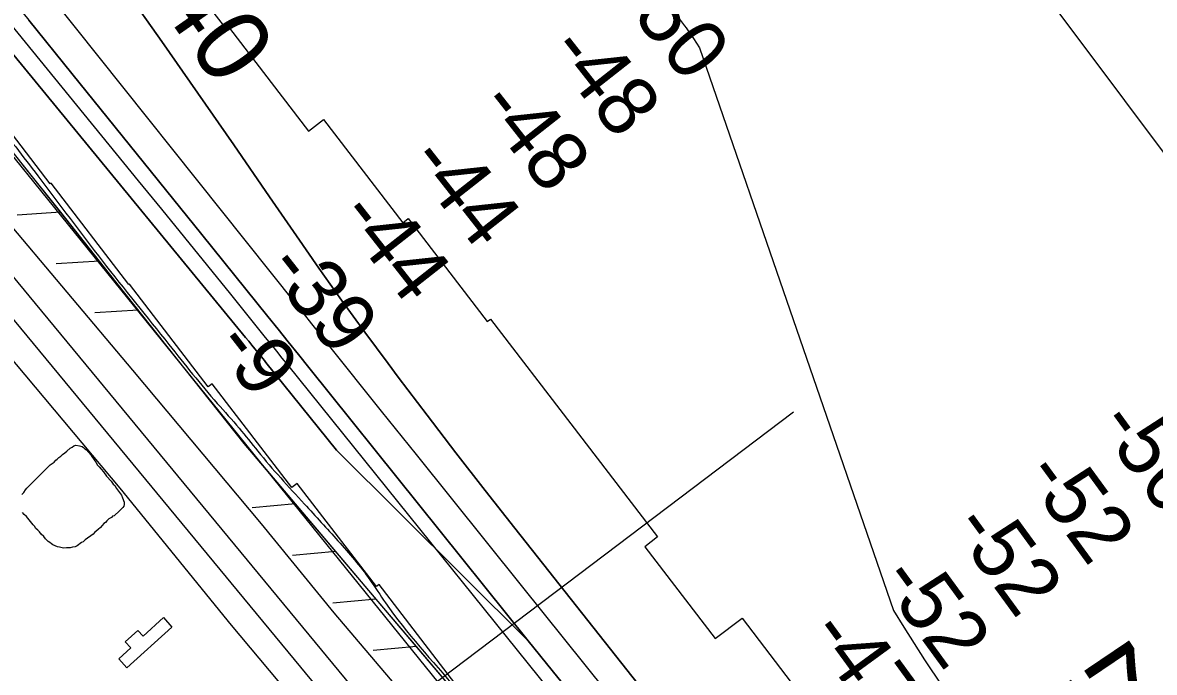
# Model space of a CAD drawing. Extents: x 3887375 to 3925618, y 296674 to 322633.
# Drawn here: x 3900685 to 3901955, y 303069 to 303798 of the extents above; entities that cross this region are included whole.
import ezdxf

# ---------------------------------------------------------------- set-up
doc = ezdxf.new("R2010")
doc.units = 0
for name, color, linetype in [('V-BLDG-OTLN', 7, 'Continuous'), ('V-LEVE-TOET', 7, 'Continuous'), ('V-RIVR-EDGE', 7, 'Continuous'), ('V-RIVR-RANG', 7, 'Continuous'), ('V-RRAP-FSHR', 7, 'Continuous'), ('V-RRAP-RVMT', 7, 'Continuous'), ('V-SITE-VEGE', 7, 'Continuous'), ('V-SURV-IDEN', 7, 'Continuous'), ('V-SURV-LINE', 7, 'Continuous'), ('V-TOPO-DPTH', 7, 'Continuous'), ('V-TOPO-MAJR', 7, 'Continuous'), ('V-TOPO-MAJR-IDEN', 7, 'Continuous'), ('V-TOPO-MINR', 7, 'Continuous')]:
    doc.layers.add(name, color=color, linetype=linetype)

msp = doc.modelspace()

# ---------------------------------------------------------------- linework, layer by layer
at = {"layer": 'V-BLDG-OTLN'}
msp.add_lwpolyline([(3900852.6, 303120.2), (3900802, 303074.5), (3900792.9, 303084.5), (3900806.5, 303096.8), (3900800.2, 303103.8), (3900814.2, 303116.5), (3900820.1, 303110.1), (3900843, 303130.8)], close=True, dxfattribs=at)
at = {"layer": 'V-LEVE-TOET'}
for points in [[(3901707.7, 302278.6), (3901647.7, 302352.6), (3901568.6, 302454.8), (3901489.4, 302571.2), (3901419.6, 302666.9), (3901350.9, 302753.6), (3901260.8, 302865.9), (3901184, 302961.1), (3901104.1, 303054.3), (3901034.7, 303136), (3900953.2, 303236.1), (3900808.8, 303408.5), (3900661.4, 303583.6), (3900535.6, 303736.4), (3900409.9, 303890.7), (3900289.1, 304039.5), (3900169.5, 304191.5), (3900063.8, 304326.3), (3899979, 304436.6), (3899860.4, 304585.9), (3899743.5, 304733.3)], [(3901593.3, 302276.6), (3901551.2, 302327.1), (3901473.8, 302430.8), (3901390.8, 302544.9), (3901295.5, 302675.3), (3901201.5, 302790.1), (3901115.9, 302885.4), (3901059.3, 302956.1), (3900993.1, 303034.3), (3900919.3, 303122.2), (3900794.4, 303275.9), (3900678.1, 303415), (3900578.2, 303534), (3900459.7, 303676.1), (3900342.1, 303815.9), (3900217.2, 303973.4), (3900106.8, 304107.3), (3900018.3, 304237.4), (3899953.6, 304320.1), (3899883.4, 304409.2), (3899779.4, 304538), (3899658.3, 304689.7)]]:
    msp.add_lwpolyline(points, dxfattribs=at)
at = {"layer": 'V-RIVR-EDGE'}
msp.add_spline([(3894498, 310522.4), (3894530, 310496.1), (3894553.8, 310474.7), (3894579.9, 310451.3), (3894614.8, 310419.2), (3894633.2, 310400.7), (3894662.8, 310372.4), (3894685.1, 310353.4), (3894692.4, 310347.1), (3894709.8, 310328.1), (3894746.6, 310285.3), (3894785.8, 310252.2), (3894809.6, 310225.9), (3894830.4, 310205.4), (3894852.7, 310189.9), (3894866.7, 310171.8), (3894915.2, 310120.3), (3894950.1, 310083.7), (3894971.4, 310062.8), (3894999, 310039.4), (3895025.2, 310017), (3895052.8, 309992.7), (3895093, 309952.3), (3895110.9, 309932.8), (3895141.4, 309903.1), (3895188.9, 309855.9), (3895222.8, 309821.3), (3895255.8, 309784.3), (3895319.2, 309722.5), (3895350.7, 309688.4), (3895358.4, 309676.3), (3895364.7, 309669.4), (3895374.9, 309663.1), (3895389, 309650.4), (3895410.8, 309628.1), (3895448.5, 309583.3), (3895480.5, 309554.1), (3895503.8, 309527.8), (3895533.8, 309499.5), (3895577.4, 309454.8), (3895606.9, 309425.5), (3895653.5, 309378.8), (3895685.9, 309349.1), (3895719.8, 309314.5), (3895749.4, 309285.8), (3895790.6, 309242.5), (3895837.1, 309195.8), (3895863.7, 309164.1), (3895900, 309127.6), (3895944.1, 309081.4), (3895955.7, 309070.7), (3895974.6, 309054.6), (3896002.3, 309033.1), (3896032.8, 309003.9), (3896062.8, 308972.3), (3896082.7, 308950.4), (3896119.5, 308911.9), (3896139.3, 308892.5), (3896152, 308889.5), (3896163.1, 308883.7), (3896167.9, 308873.9), (3896170.3, 308862.3), (3896184.4, 308844.3), (3896211, 308816), (3896224.1, 308810.2), (3896236.7, 308802.4), (3896249.8, 308786.8), (3896255.6, 308776.6), (3896270.6, 308766.4), (3896280.3, 308753.2), (3896295.8, 308737.2), (3896375.3, 308661.2), (3896425.2, 308610.1), (3896464.4, 308570.6), (3896519.6, 308515.6), (3896548.7, 308483), (3896563.2, 308467.5), (3896597.6, 308430.9), (3896635.9, 308396.4), (3896666.4, 308365.7), (3896681.4, 308349.6), (3896712.4, 308320.4), (3896746.3, 308287.3), (3896777.4, 308260), (3896801.6, 308235.7), (3896820.5, 308215.3), (3896842.8, 308195.3), (3896851.5, 308181.2), (3896882.5, 308148.6), (3896918.8, 308116.4), (3896962.9, 308074.6), (3896997.8, 308033.2), (3897029.2, 307998.6), (3897042.3, 307985), (3897083.5, 307945.6), (3897107.2, 307918.3), (3897123.2, 307898.8), (3897130, 307898.8), (3897142.1, 307893), (3897146, 307882.3), (3897149.9, 307874), (3897162.9, 307860.4), (3897188.6, 307833.1), (3897229.3, 307788.8), (3897267.6, 307752.3), (3897300.5, 307715.8), (3897334.4, 307680.3), (3897361.5, 307651.1), (3897384.8, 307628.2), (3897411.4, 307599), (3897445.8, 307563.4), (3897494.3, 307516.7), (3897543.2, 307462.7), (3897584.8, 307418.4), (3897609, 307394), (3897646.8, 307355.6), (3897678.8, 307323.9), (3897715.1, 307290.3), (3897752, 307253.3), (3897767, 307236.3), (3897837.7, 307158.4), (3897886.6, 307104.4), (3897936, 307048.4), (3897965.5, 307015.3), (3898010.6, 306970.1), (3898027.5, 306949.1), (3898045, 306936), (3898063.9, 306914.1), (3898089, 306882.5), (3898117.1, 306854.7), (3898160.2, 306801.2), (3898195.6, 306763.7), (3898235.8, 306719.9), (3898261.5, 306693.6), (3898297.3, 306650.8), (3898332.7, 306612.3), (3898369.9, 306568), (3898397.5, 306534.9), (3898422.2, 306505.8), (3898462.9, 306455.1), (3898495.3, 306417.2), (3898522, 306382.2), (3898601.4, 306284.3), (3898652.2, 306228.4), (3898693.4, 306177.3), (3898729.7, 306130.6), (3898777.1, 306074.1), (3898825.5, 306014.3), (3898848.8, 305986), (3898904, 305917.4), (3898957.2, 305854.7), (3898984.4, 305818.2), (3899049.7, 305744.7), (3899107.8, 305679.4), (3899129.1, 305651.7), (3899142.7, 305630.3), (3899156.2, 305611.8), (3899175.1, 305588), (3899224, 305529.6), (3899256, 305493.6), (3899288.9, 305449.3), (3899312.6, 305415.2), (3899375.6, 305336.9), (3899410.9, 305296), (3899442.8, 305252.2), (3899470.4, 305211.9), (3899531.4, 305133.5), (3899579.3, 305071.2), (3899616.1, 305026), (3899647.1, 304986.1), (3899690.7, 304931.1), (3899729.4, 304876.6), (3899753.6, 304846.9), (3899770.6, 304821.6), (3899817.5, 304755.5), (3899845.6, 304713.2), (3899868.3, 304677.2), (3899889.6, 304650.4), (3899911.4, 304623.6), (3899955.4, 304569.1), (3899987.4, 304526.8), (3900012.6, 304494.2), (3900025.6, 304476.2), (3900037.2, 304456.8), (3900061.9, 304431.9), (3900070.7, 304424.1), (3900074.5, 304414.4), (3900075, 304404.2), (3900073, 304397.9), (3900071.5, 304388.7), (3900071.5, 304383.8), (3900075.9, 304379), (3900087.1, 304374.1), (3900096.3, 304367.7), (3900108.4, 304362.4), (3900117.1, 304353.6), (3900140.8, 304326.3), (3900165.5, 304299.1), (3900226.1, 304227.6), (3900277.9, 304164.3), (3900320, 304105.9), (3900352.4, 304062.6), (3900384.4, 304023.2), (3900411.5, 303988.2), (3900438.1, 303954.1), (3900462.8, 303926.8), (3900556.2, 303812.5), (3900597.9, 303762.9), (3900633.7, 303716.6), (3900652.6, 303691.3), (3900702, 303626.6), (3900774.6, 303530.8), (3900849.1, 303437.3), (3900903.4, 303371.2), (3900928.1, 303343.4), (3900948.9, 303317.6), (3901001.2, 303258.3), (3901038.9, 303216.9), (3901074.8, 303173.1), (3901092.2, 303147.3), (3901171.6, 303050.5), (3901205, 303008.6), (3901238.4, 302968.2), (3901274.7, 302927.8), (3901303.3, 302893.8), (3901344, 302847.5), (3901366.7, 302816.4), (3901404.5, 302770.2), (3901454.4, 302715.2), (3901507.2, 302659.2), (3901551.7, 302608.1), (3901584.7, 302570.6), (3901650, 302491.3), (3901681, 302443.6), (3901717.8, 302388.2), (3901785.5, 302298.2), (3901789.5, 302293.3)], degree=3, dxfattribs=at)
at = {"layer": 'V-RIVR-RANG'}
msp.add_line((3901087.4, 303011.9), (3901550.1, 303361.6), dxfattribs=at)
at = {"layer": 'V-RRAP-FSHR'}
for p, q in [((3900727.8, 303585.6), (3900679, 303582.6)), ((3900771.3, 303530.7), (3900722.6, 303527.8)), ((3900814.8, 303475.9), (3900766.1, 303473)), ((3900991.2, 303258.5), (3900942.6, 303254)), ((3901036.5, 303205.1), (3900987.8, 303200.6)), ((3901081.7, 303151.7), (3901033.1, 303147.2)), ((3901127, 303098.3), (3901078.4, 303093.8))]:
    msp.add_line(p, q, dxfattribs=at)
for points in [[(3891468.4, 312810.1), (3891592.1, 312735.5), (3892299.9, 312230.2), (3893039.2, 311719.3), (3893631.6, 311277.1), (3894117.7, 310846), (3894636.9, 310371.6), (3895242, 309786.8), (3895348.8, 309658.3), (3895604.3, 309398.3), (3896430.2, 308555.1), (3897023.9, 307973.7), (3897641.6, 307335.1), (3898033.6, 306930.9), (3898562.2, 306317.9), (3899280.4, 305434.2), (3899629.7, 304981.5), (3900046.2, 304414.8), (3900422.7, 303959.4), (3901188.8, 303011.8), (3901775.8, 302279.8)], [(3901789.3, 302283.8), (3901580.6, 302550.1), (3901486.3, 302669.7), (3901336.9, 302850.8), (3900933.8, 303326.1), (3900183.2, 304271.3)], [(3900727.8, 303585.6), (3900684.2, 303640.4)], [(3900771.3, 303530.7), (3900727.8, 303585.6)], [(3900814.8, 303475.9), (3900771.3, 303530.7)], [(3900840.5, 303443.6), (3900814.8, 303475.9)], [(3900991.2, 303258.5), (3900945.9, 303311.9)], [(3901036.5, 303205.1), (3900991.2, 303258.5)], [(3901081.7, 303151.7), (3901036.5, 303205.1)], [(3901127, 303098.3), (3901081.7, 303151.7)], [(3901172.3, 303044.9), (3901127, 303098.3)]]:
    msp.add_lwpolyline(points, dxfattribs=at)
at = {"layer": 'V-RRAP-RVMT'}
for p, q in [((3900827.2, 303903.9), (3900914.2, 303790.3)), ((3900914.2, 303790.3), (3900917, 303792.4)), ((3900917, 303792.4), (3901005.7, 303676.7)), ((3900716, 303617.4), (3900627.6, 303732.8)), ((3901005.7, 303676.7), (3901022.8, 303689.7)), ((3901022.8, 303689.7), (3901111.5, 303573.9)), ((3900717, 303618.3), (3900716, 303617.4)), ((3900804.2, 303504.5), (3900717, 303618.3)), ((3901111.5, 303573.9), (3901117.7, 303578.7)), ((3901117.7, 303578.7), (3901206.4, 303463)), ((3900804.8, 303504.9), (3900804.2, 303504.5)), ((3900893.2, 303389.6), (3900804.8, 303504.9)), ((3901206.4, 303463), (3901209.9, 303465.7)), ((3901209.9, 303465.7), (3901300, 303348.1)), ((3900897.8, 303393.1), (3900893.2, 303389.6)), ((3900987, 303276.8), (3900897.8, 303393.1)), ((3901300, 303348.1), (3901397.3, 303221.3)), ((3900993.2, 303281.5), (3900987, 303276.8)), ((3901082.1, 303165.6), (3900993.2, 303281.5)), ((3901397.3, 303221.3), (3901383.2, 303210.4)), ((3901383.2, 303210.4), (3901462.3, 303107.2)), ((3901085, 303167.9), (3901082.1, 303165.6)), ((3901174.8, 303050.8), (3901085, 303167.9)), ((3901462.3, 303107.2), (3901492.4, 303130.1)), ((3901492.4, 303130.1), (3901589.5, 303003.4))]:
    msp.add_line(p, q, dxfattribs=at)
at = {"layer": 'V-SITE-VEGE'}
msp.add_lwpolyline([(3900684.2, 303268.9), (3900686.2, 303271.3), (3900688.2, 303274.2), (3900689.8, 303276.2), (3900694.5, 303281.1), (3900696.9, 303283.1), (3900709.6, 303296), (3900711.9, 303298.1), (3900715.9, 303302.1), (3900720.3, 303305.4), (3900722.3, 303307.4), (3900723.8, 303308.6), (3900725.8, 303310.6), (3900727.8, 303311.9), (3900729.8, 303313.9), (3900732.2, 303315.9), (3900734.6, 303317.5), (3900738.5, 303320.8), (3900740.5, 303322), (3900742.5, 303323.6), (3900744.9, 303324.5), (3900748.9, 303323.7), (3900751.7, 303322.9), (3900753.3, 303321.8), (3900755, 303320.2), (3900756.6, 303319), (3900761.4, 303313.4), (3900762.7, 303311.5), (3900764.7, 303309.1), (3900765.9, 303306.7), (3900767.1, 303305.1), (3900769.2, 303301.9), (3900770.8, 303299.9), (3900773.2, 303297.5), (3900775.7, 303294.4), (3900779.3, 303289.6), (3900784.2, 303284.1), (3900786.6, 303280.5), (3900788.3, 303278.9), (3900790.3, 303275.7), (3900796, 303268.2), (3900797.2, 303265.4), (3900798.9, 303260.2), (3900798.9, 303257.8), (3900798.5, 303255.8), (3900797.3, 303254.2), (3900793.8, 303250.5), (3900787.8, 303245.2), (3900785.8, 303244.8), (3900784.6, 303243.2), (3900781.9, 303241.6), (3900779.5, 303239.5), (3900777.9, 303237.5), (3900776.3, 303236.3), (3900774.3, 303234.3), (3900772.4, 303231.9), (3900769.6, 303229.8), (3900767.6, 303227.8), (3900766, 303226.6), (3900764, 303224.6), (3900755.3, 303218.1), (3900752.9, 303216), (3900750.9, 303215.2), (3900746.2, 303211.5), (3900743.8, 303210.3), (3900741, 303209.9), (3900738.2, 303209.1), (3900734.2, 303209), (3900731.4, 303208.6), (3900729.4, 303209), (3900726.5, 303209.7), (3900724.1, 303210.1), (3900721.7, 303211.3), (3900718.9, 303212.4), (3900717.3, 303213.6), (3900715.7, 303215.2), (3900713.7, 303216.4), (3900710.8, 303219.2), (3900708.8, 303221.9), (3900706, 303224.3), (3900703.9, 303227.1), (3900701.9, 303229.1), (3900699.9, 303230.7), (3900698.2, 303233.4), (3900697, 303235), (3900689.3, 303244.2), (3900686.9, 303246.5), (3900684.9, 303248.9)], dxfattribs=at)
at = {"layer": 'V-SURV-LINE'}
for points in [[(3900476.9, 303751.8), (3901318.4, 302733.5)], [(3901295.2, 302714.4), (3900453.8, 303732.6)]]:
    msp.add_lwpolyline(points, dxfattribs=at)
at = {"layer": 'V-TOPO-DPTH'}
for points in [[(3899996.1, 304666.3), (3900007, 304652.8), (3900017.9, 304639.3), (3900200.6, 304411.9), (3900246.8, 304354.3), (3900293, 304296.8), (3900339.1, 304239.2), (3900385.2, 304181.5), (3900439.6, 304113.3), (3900458.5, 304089.8), (3900477.3, 304066.3), (3900496.2, 304042.8), (3900515.2, 304019.4), (3900691.8, 303801.4), (3900740.4, 303741.2), (3900789, 303681.1), (3900837.6, 303620.9), (3900886.1, 303560.7), (3900960, 303468.8), (3900971.6, 303454.5), (3900983.1, 303440.2), (3900994.6, 303425.9), (3901006.1, 303411.6), (3901252.4, 303104.9)], [(3901252.4, 303104.9), (3901037.1, 303318.9), (3900958, 303417.1), (3900957.2, 303418.2), (3900956.3, 303419.3), (3900954.6, 303421.4), (3900949.3, 303428), (3900945.7, 303432.3), (3900942.2, 303436.6), (3900938.7, 303440.9), (3900935.1, 303445.3), (3900486.7, 303991.6), (3900409.6, 304087.8)], [(3900687.7, 303863.7), (3900990.3, 303484.2), (3900999.7, 303472.4), (3901009.1, 303460.6), (3901018.6, 303448.8), (3901028, 303437), (3901087.5, 303362.6), (3901126.6, 303313.7), (3901165.8, 303264.7), (3901205.1, 303215.8), (3901244.3, 303166.9), (3901411.8, 302958.6), (3901426.4, 302940.7), (3901441.2, 302922.9), (3901456.2, 302905.4), (3901471.4, 302887.9), (3901558, 302789.9), (3901587.8, 302757.3), (3901946.4, 302370.6), (3901982.7, 302326)], [(3900687.7, 303863.7), (3900990.3, 303484.2), (3900999.7, 303472.4), (3901009.1, 303460.6), (3901018.6, 303448.8), (3901028, 303437), (3901087.5, 303362.6), (3901126.6, 303313.7), (3901165.8, 303264.7), (3901205.1, 303215.8), (3901244.3, 303166.9), (3901411.8, 302958.6), (3901426.4, 302940.7), (3901441.2, 302922.9), (3901456.2, 302905.4), (3901471.4, 302887.9), (3901558, 302789.9), (3901587.8, 302757.3), (3901946.4, 302370.6), (3901982.7, 302326)], [(3901955.2, 302446.5), (3901501.7, 302905.5), (3901489.7, 302917.2), (3901476.5, 302931), (3901471.6, 302936.2), (3901466.8, 302941.5), (3901462.2, 302947), (3901457.7, 302952.5), (3901237.3, 303231.2), (3901204.2, 303273.3), (3901171.3, 303315.6), (3901138.8, 303358.1), (3901106.5, 303400.8), (3901095.2, 303415.8), (3901068.9, 303451.3), (3901042.9, 303487), (3901017.5, 303523), (3900992.3, 303559.2), (3900962.2, 303603.1), (3900922.1, 303661.3), (3900881.8, 303719.4), (3900841.1, 303777.3), (3900800.3, 303835.1)], [(3901955.2, 302446.5), (3901501.7, 302905.5), (3901489.7, 302917.2), (3901476.5, 302931), (3901471.6, 302936.2), (3901466.8, 302941.5), (3901462.2, 302947), (3901457.7, 302952.5), (3901237.3, 303231.2), (3901204.2, 303273.3), (3901171.3, 303315.6), (3901138.8, 303358.1), (3901106.5, 303400.8), (3901095.2, 303415.8), (3901068.9, 303451.3), (3901042.9, 303487), (3901017.5, 303523), (3900992.3, 303559.2), (3900962.2, 303603.1), (3900922.1, 303661.3), (3900881.8, 303719.4), (3900841.1, 303777.3), (3900800.3, 303835.1)], [(3901306.4, 303037.7), (3901279.4, 303071.3), (3901252.4, 303104.9), (3901006.1, 303411.6), (3900994.6, 303425.9), (3900983.1, 303440.2), (3900971.6, 303454.5), (3900960, 303468.8), (3900886.1, 303560.7), (3900837.6, 303620.9), (3900789, 303681.1), (3900740.4, 303741.2), (3900691.8, 303801.4)]]:
    msp.add_lwpolyline(points, dxfattribs=at)
at = {"layer": 'V-TOPO-MAJR'}
msp.add_lwpolyline([(3901411, 303817.5), (3901427.9, 303794.9), (3901429.6, 303792.7), (3901431.2, 303790.4), (3901432.7, 303788.2), (3901434.3, 303785.9), (3901444.5, 303770.3), (3901662.4, 303138.7), (3901673.8, 303120.1), (3901685.4, 303101.6), (3901697.2, 303083.4), (3902082.5, 302508.4)], dxfattribs=at)
at = {"layer": 'V-TOPO-MINR'}
for points in [[(3901230.9, 304657.4), (3901234.4, 304653.1), (3901237.9, 304648.6), (3901241.4, 304644.2), (3901244.8, 304639.7), (3901248.2, 304635.2), (3901251.5, 304630.7), (3901254.8, 304626.1), (3901674.5, 304043.1), (3901688.9, 304023.1), (3901703.4, 304003.2), (3901718, 303983.4), (3901732.7, 303963.7), (3902015.2, 303585.9)], [(3900409.6, 304087.8), (3900486.7, 303991.6), (3900935.1, 303445.3), (3900938.7, 303440.9), (3900942.2, 303436.6), (3900945.7, 303432.3), (3900949.3, 303428), (3900954.6, 303421.4), (3900956.3, 303419.3), (3900957.2, 303418.2), (3900958, 303417.1), (3901037.1, 303318.9)], [(3900508.1, 303997.1), (3900814.8, 303620.9), (3900840.7, 303589.1), (3900866.6, 303557.3), (3900892.4, 303525.5), (3900918.2, 303493.6), (3900957.3, 303445.3), (3900963.5, 303437.5), (3900969.8, 303429.8), (3900976, 303422.1), (3900982.2, 303414.4), (3901363.4, 302940.9)], [(3900687.7, 303863.7), (3900990.3, 303484.2), (3900999.7, 303472.4), (3901009.1, 303460.6), (3901018.6, 303448.8), (3901028, 303437), (3901087.5, 303362.6), (3901126.6, 303313.7), (3901165.8, 303264.7), (3901205.1, 303215.8), (3901244.3, 303166.9), (3901411.8, 302958.6), (3901426.4, 302940.7), (3901441.2, 302922.9), (3901456.2, 302905.4), (3901471.4, 302887.9), (3901558, 302789.9), (3901587.8, 302757.3), (3901946.4, 302370.6), (3901982.7, 302326)], [(3900800.3, 303835.1), (3900841.1, 303777.3), (3900881.8, 303719.4), (3900922.1, 303661.3), (3900962.2, 303603.1), (3900992.3, 303559.2), (3901017.5, 303523), (3901042.9, 303487), (3901068.9, 303451.3), (3901095.2, 303415.8), (3901106.5, 303400.8), (3901138.8, 303358.1), (3901171.3, 303315.6), (3901204.2, 303273.3), (3901237.3, 303231.2), (3901457.7, 302952.5), (3901462.2, 302947), (3901466.8, 302941.5), (3901471.6, 302936.2), (3901476.5, 302931), (3901489.7, 302917.2), (3901501.7, 302905.5), (3901955.2, 302446.5)], [(3900691.8, 303801.4), (3900740.4, 303741.2), (3900789, 303681.1), (3900837.6, 303620.9), (3900886.1, 303560.7), (3900960, 303468.8), (3900971.6, 303454.5), (3900983.1, 303440.2), (3900994.6, 303425.9), (3901006.1, 303411.6), (3901252.4, 303104.9), (3901279.4, 303071.3), (3901306.4, 303037.7)]]:
    msp.add_lwpolyline(points, dxfattribs=at)

# ---------------------------------------------------------------- texts
at = {"layer": 'V-RIVR-RANG'}
for s, rotation, p in [('-50', 308.1531, (3901350.3, 303830.3)), ('-48', 308.1531, (3901273, 303766.8)), ('-48', 308.1531, (3901194.2, 303705.2)), ('-44', 308.1531, (3901115.9, 303643)), ('-44', 308.1531, (3901037.1, 303581.5)), ('-39', 308.1531, (3900956.1, 303522.8)), ('-9', 307.8683, (3900897.6, 303435.8)), ('-56', 306.14, (3901889.1, 303347.6)), ('-52', 306.14, (3901806.6, 303291)), ('-52', 306.14, (3901725.7, 303232.2)), ('-52', 306.14, (3901644.8, 303173.4)), ('-47', 306.14, (3901565.1, 303112.9))]:
    msp.add_text(s, height=67, rotation=rotation, dxfattribs=at).set_placement(p)
at = {"layer": 'V-SURV-IDEN'}
msp.add_text('1575+57.9', height=100, rotation=34.0387, dxfattribs=at).set_placement((3901553.6, 302732.6))
at = {"layer": 'V-TOPO-MAJR-IDEN'}
msp.add_text('-40', height=83, rotation=305.0634, dxfattribs=at).set_placement((3900812.2, 303854.7))

doc.saveas('drawing.dxf')
